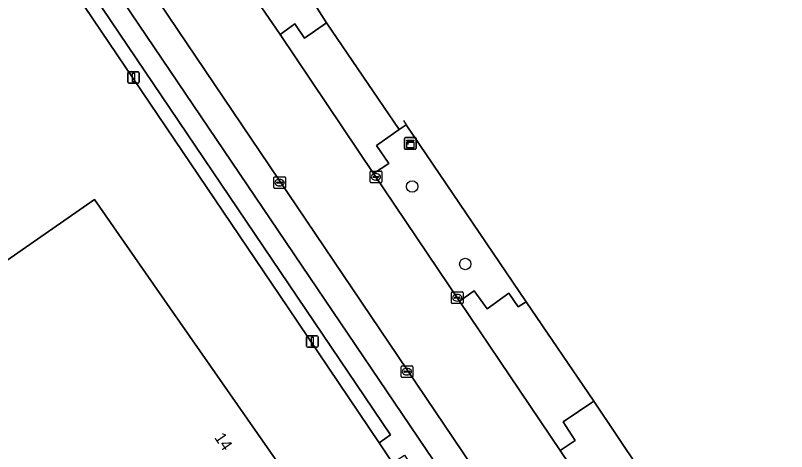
# Model space of a CAD drawing. Extents: x 156702 to 158052, y 387630 to 388992.
# Drawn here: x 157369.7 to 157436.1, y 387987.6 to 388025.2 of the extents above; entities that cross this region are included whole.
import ezdxf

# ---------------------------------------------------------------- set-up
doc = ezdxf.new("R2010")
doc.units = 0
for name, color, linetype in [('IMGEO_Berm_groen', 7, 'Continuous'), ('IMGEO_Boom', 7, 'Continuous'), ('IMGEO_Erf', 7, 'Continuous'), ('IMGEO_Groenvoorziening', 7, 'Continuous'), ('IMGEO_Hek', 7, 'Continuous'), ('IMGEO_Kast', 7, 'Continuous'), ('IMGEO_Kolk', 7, 'Continuous'), ('IMGEO_Lichtmast', 7, 'Continuous'), ('IMGEO_Pand', 7, 'Continuous'), ('IMGEO_Pand_nummerreeks', 7, 'Continuous'), ('IMGEO_Parkeervlak_open', 7, 'Continuous'), ('IMGEO_Rijbaan_lokaal_gesloten', 7, 'Continuous'), ('IMGEO_Rijbaan_lokaal_open', 7, 'Continuous'), ('IMGEO_Voetpad_open', 7, 'Continuous')]:
    doc.layers.add(name, color=color, linetype=linetype)

msp = doc.modelspace()

# ---------------------------------------------------------------- linework, layer by layer
at = {"layer": 'IMGEO_Berm_groen'}
for points in [[(157387.19, 388039.182), (157379.198, 388048.04), (157377.897, 388047.012), (157379.097, 388045.532), (157377.848, 388044.562), (157380.459, 388041.129), (157392.527, 388023.508), (157393.764, 388024.429), (157394.61, 388023.215), (157396.502, 388024.511)], [(157403.363, 388015.762), (157402.741, 388015.343), (157400.789, 388013.975), (157401.855, 388012.429), (157400.555, 388011.557), (157407.925, 388000.59), (157409.211, 388001.471), (157410.319, 387999.926), (157412.192, 388001.265), (157412.973, 388000.104), (157413.667, 388000.525)], [(157419.496, 387991.988), (157416.861, 387990.191), (157417.893, 387988.603), (157416.586, 387987.739), (157420.098, 387982.532), (157423.609, 387977.326), (157424.882, 387978.233), (157426.84, 387975.471), (157429.376, 387977.195)]]:
    msp.add_lwpolyline(points, close=True, dxfattribs=at)
at = {"layer": 'IMGEO_Boom'}
for centre in [(157403.868, 388010.441), (157408.434, 388003.776)]:
    msp.add_circle(centre, 0.489, dxfattribs=at)
at = {"layer": 'IMGEO_Erf'}
for points in [[(157387.19, 388039.182), (157396.502, 388024.511), (157402.741, 388015.343), (157403.363, 388015.762), (157413.667, 388000.525), (157419.496, 387991.988), (157429.376, 387977.195), (157434.667, 387969.272), (157436.067, 387967.176), (157433.406, 387964.883), (157433.59, 387964.667), (157433.73, 387964.762), (157434.042, 387964.343), (157428.255, 387959.385), (157427.905, 387959.765), (157428.127, 387959.953), (157427.939, 387960.171), (157427.645, 387960.512), (157423.765, 387957.199), (157400.278, 387936.844), (157388.261, 387926.646), (157368.779, 387910.004)], [(157410.18, 387974.784), (157402.177, 387986.679), (157401.025, 387988.392), (157393.215, 388000), (157371.506, 388032.159), (157369.928, 388034.292)], [(157368.332, 388003.627), (157376.541, 388009.329), (157383.04, 388000), (157393.139, 387985.505), (157395.632, 387981.926), (157397.057, 387982.917), (157398.504, 387980.872), (157399.026, 387981.234), (157403.012, 387975.51), (157402.494, 387975.151), (157405.159, 387971.263), (157401.506, 387968.719), (157398.499, 387966.625), (157378.578, 387952.75), (157377.05, 387954.95), (157374.897, 387958.052), (157370.981, 387963.692), (157367.677, 387961.4)]]:
    msp.add_lwpolyline(points, dxfattribs=at)
at = {"layer": 'IMGEO_Groenvoorziening'}
msp.add_lwpolyline([(157372.113, 388033.384), (157370.953, 388035.05), (157369.928, 388034.292), (157371.506, 388032.159), (157393.215, 388000), (157401.025, 387988.392), (157402.016, 387989.08)], close=True, dxfattribs=at)
at = {"layer": 'IMGEO_Hek'}
for points in [[(157403.125, 388016.114), (157403.363, 388015.762)], [(157403.363, 388015.762), (157413.667, 388000.525)], [(157413.667, 388000.525), (157419.496, 387991.988)], [(157419.496, 387991.988), (157436.067, 387967.176)]]:
    msp.add_lwpolyline(points, dxfattribs=at)
at = {"layer": 'IMGEO_Kast'}
for p, q in [((157403.214, 388013.726), (157403.214, 388014.567)), ((157403.214, 388014.567), (157403.214, 388013.726)), ((157403.289, 388014.651), (157404.13, 388014.651)), ((157404.13, 388014.651), (157403.289, 388014.651)), ((157404.214, 388014.576), (157404.214, 388013.735)), ((157404.214, 388013.735), (157404.214, 388014.576)), ((157404.139, 388013.651), (157403.298, 388013.651)), ((157403.298, 388013.651), (157404.139, 388013.651))]:
    msp.add_line(p, q, dxfattribs=at)
for points in [[(157403.409, 388014.441), (157404.009, 388014.441), (157404.009, 388014.356), (157403.409, 388014.356), (157403.409, 388014.441)], [(157403.409, 388014.266), (157404.009, 388014.266), (157404.009, 388013.777), (157403.409, 388013.777), (157403.409, 388014.266)]]:
    msp.add_lwpolyline(points, dxfattribs=at)
msp.add_circle((157403.493, 388014.115), 0.0377, dxfattribs=at)
for centre, start, end in [((157403.292, 388014.573), 92.4484, 184.28452), ((157403.292, 388014.573), 92.4484, 184.28452), ((157404.136, 388014.573), 2.4484, 94.28452), ((157404.136, 388014.573), 2.4484, 94.28452), ((157403.292, 388013.729), 182.4484, 274.28452), ((157403.292, 388013.729), 182.4484, 274.28452), ((157404.136, 388013.729), 272.4484, 4.28452), ((157404.136, 388013.729), 272.4484, 4.28452)]:
    msp.add_arc(centre, 0.0779, start, end, dxfattribs=at)
at = {"layer": 'IMGEO_Kolk'}
for p, q in [((157400.25, 388010.848), (157400.25, 388011.7)), ((157400.325, 388011.774), (157401.177, 388011.774)), ((157400.738, 388011.554), (157400.763, 388011.554)), ((157401.251, 388011.7), (157401.251, 388010.848)), ((157391.963, 388010.353), (157391.963, 388011.205)), ((157392.038, 388011.279), (157392.89, 388011.279)), ((157392.222, 388010.773), (157392.222, 388010.785)), ((157392.265, 388010.822), (157392.663, 388010.822)), ((157392.451, 388011.059), (157392.476, 388011.059)), ((157392.706, 388010.785), (157392.706, 388010.773)), ((157392.964, 388011.205), (157392.964, 388010.353)), ((157401.177, 388010.774), (157400.325, 388010.774)), ((157400.509, 388011.268), (157400.509, 388011.28)), ((157400.947, 388011.231), (157400.549, 388011.231)), ((157400.552, 388011.317), (157400.95, 388011.317)), ((157400.761, 388010.994), (157400.736, 388010.994)), ((157400.993, 388011.28), (157400.993, 388011.268)), ((157392.89, 388010.279), (157392.038, 388010.279)), ((157392.66, 388010.736), (157392.262, 388010.736)), ((157392.474, 388010.499), (157392.449, 388010.499)), ((157407.24, 388000.446), (157407.24, 388001.298)), ((157407.315, 388001.372), (157408.167, 388001.372)), ((157407.499, 388000.866), (157407.499, 388000.878)), ((157407.937, 388000.829), (157407.539, 388000.829)), ((157407.542, 388000.915), (157407.94, 388000.915)), ((157407.728, 388001.152), (157407.753, 388001.152)), ((157407.983, 388000.878), (157407.983, 388000.866)), ((157408.241, 388001.298), (157408.241, 388000.446)), ((157408.167, 388000.372), (157407.315, 388000.372)), ((157407.751, 388000.592), (157407.726, 388000.592)), ((157402.917, 387994.091), (157402.917, 387994.943)), ((157402.992, 387995.017), (157403.844, 387995.017)), ((157403.918, 387994.943), (157403.918, 387994.091)), ((157403.176, 387994.511), (157403.176, 387994.523)), ((157403.614, 387994.474), (157403.216, 387994.474)), ((157403.219, 387994.56), (157403.617, 387994.56)), ((157403.428, 387994.237), (157403.403, 387994.237)), ((157403.405, 387994.797), (157403.43, 387994.797)), ((157403.66, 387994.523), (157403.66, 387994.511)), ((157403.844, 387994.017), (157402.992, 387994.017))]:
    msp.add_line(p, q, dxfattribs=at)
for points in [[(157400.25, 388010.848), (157400.25, 388011.7)], [(157400.325, 388011.774), (157401.177, 388011.774)], [(157401.251, 388011.7), (157401.251, 388010.848)], [(157391.963, 388010.353), (157391.963, 388011.205)], [(157392.038, 388011.279), (157392.89, 388011.279)], [(157392.964, 388011.205), (157392.964, 388010.353)], [(157401.177, 388010.774), (157400.325, 388010.774)], [(157392.89, 388010.279), (157392.038, 388010.279)], [(157407.24, 388000.446), (157407.24, 388001.298)], [(157407.315, 388001.372), (157408.167, 388001.372)], [(157408.241, 388001.298), (157408.241, 388000.446)], [(157408.167, 388000.372), (157407.315, 388000.372)], [(157402.917, 387994.091), (157402.917, 387994.943)], [(157402.992, 387995.017), (157403.844, 387995.017)], [(157403.918, 387994.943), (157403.918, 387994.091)], [(157403.844, 387994.017), (157402.992, 387994.017)]]:
    msp.add_lwpolyline(points, dxfattribs=at)
for centre, radius, start, end in [((157400.327, 388011.698), 0.0765, 91.55205, 178.44795), ((157400.327, 388011.698), 0.0765, 91.55205, 178.44795), ((157401.175, 388011.698), 0.0765, 1.55205, 88.44795), ((157401.175, 388011.698), 0.0765, 1.55205, 88.44795), ((157392.04, 388011.203), 0.0765, 91.55205, 178.44795), ((157392.04, 388011.203), 0.0765, 91.55205, 178.44795), ((157392.262, 388010.782), 0.0403, 85.87752, 175.75265), ((157392.259, 388010.772), 0.0366, 178.93798, 274.71019), ((157392.663, 388010.779), 0.043, 264.86636, 352.45326), ((157392.667, 388010.784), 0.0386, 1.73085, 96.63898), ((157392.888, 388011.203), 0.0765, 1.55205, 88.44795), ((157392.888, 388011.203), 0.0765, 1.55205, 88.44795), ((157400.327, 388010.85), 0.0765, 181.55205, 268.44795), ((157400.327, 388010.85), 0.0765, 181.55205, 268.44795), ((157400.549, 388011.277), 0.0403, 85.87752, 175.75265), ((157400.546, 388011.267), 0.0366, 178.93798, 274.71019), ((157400.95, 388011.274), 0.043, 264.86636, 352.45326), ((157400.954, 388011.279), 0.0386, 1.73085, 96.63898), ((157401.175, 388010.85), 0.0765, 271.55205, 358.44795), ((157401.175, 388010.85), 0.0765, 271.55205, 358.44795), ((157392.04, 388010.355), 0.0765, 181.55205, 268.44795), ((157392.04, 388010.355), 0.0765, 181.55205, 268.44795), ((157392.888, 388010.355), 0.0765, 271.55205, 358.44795), ((157392.888, 388010.355), 0.0765, 271.55205, 358.44795), ((157407.317, 388001.296), 0.0765, 91.55205, 178.44795), ((157407.317, 388001.296), 0.0765, 91.55205, 178.44795), ((157407.539, 388000.875), 0.0403, 85.87752, 175.75265), ((157407.536, 388000.865), 0.0366, 178.93798, 274.71019), ((157407.94, 388000.872), 0.043, 264.86636, 352.45326), ((157407.944, 388000.877), 0.0386, 1.73085, 96.63898), ((157408.165, 388001.296), 0.0765, 1.55205, 88.44795), ((157408.165, 388001.296), 0.0765, 1.55205, 88.44795), ((157407.317, 388000.448), 0.0765, 181.55205, 268.44795), ((157407.317, 388000.448), 0.0765, 181.55205, 268.44795), ((157408.165, 388000.448), 0.0765, 271.55205, 358.44795), ((157408.165, 388000.448), 0.0765, 271.55205, 358.44795), ((157402.994, 387994.941), 0.0765, 91.55205, 178.44795), ((157402.994, 387994.941), 0.0765, 91.55205, 178.44795), ((157403.842, 387994.941), 0.0765, 1.55205, 88.44795), ((157403.842, 387994.941), 0.0765, 1.55205, 88.44795), ((157403.216, 387994.52), 0.0403, 85.87752, 175.75265), ((157403.213, 387994.51), 0.0366, 178.93798, 274.71019), ((157403.617, 387994.517), 0.043, 264.86636, 352.45326), ((157403.621, 387994.522), 0.0386, 1.73085, 96.63898), ((157402.994, 387994.093), 0.0765, 181.55205, 268.44795), ((157402.994, 387994.093), 0.0765, 181.55205, 268.44795), ((157403.842, 387994.093), 0.0765, 271.55205, 358.44795), ((157403.842, 387994.093), 0.0765, 271.55205, 358.44795)]:
    msp.add_arc(centre, radius, start, end, dxfattribs=at)
for centre, major_axis, ratio, start_param, end_param in [((157400.737, 388011.274), (-0.387, 0.002), 0.722429, 4.712389, 7.853982), ((157400.762, 388011.274), (-0.39, 0.002), 0.717154, 1.570796, 4.712389), ((157392.45, 388010.779), (-0.387, 0.002), 0.722429, 4.712389, 7.853982), ((157392.475, 388010.779), (-0.39, 0.002), 0.717154, 1.570796, 4.712389), ((157407.727, 388000.872), (-0.387, 0.002), 0.722429, 4.712389, 7.853982), ((157407.752, 388000.872), (-0.39, 0.002), 0.717154, 1.570796, 4.712389), ((157403.404, 387994.517), (-0.387, 0.002), 0.722429, 4.712389, 7.853982), ((157403.429, 387994.517), (-0.39, 0.002), 0.717154, 1.570796, 4.712389)]:
    msp.add_ellipse(centre, major_axis=major_axis, ratio=ratio, start_param=start_param, end_param=end_param, dxfattribs=at)
at = {"layer": 'IMGEO_Lichtmast'}
for p, q in [((157379.409, 388019.423), (157379.409, 388020.223)), ((157379.409, 388020.223), (157379.409, 388019.423)), ((157379.509, 388020.323), (157380.299, 388020.323)), ((157380.299, 388020.323), (157379.509, 388020.323)), ((157380.399, 388020.223), (157380.399, 388019.423)), ((157380.399, 388019.423), (157380.399, 388020.223)), ((157380.299, 388019.323), (157379.509, 388019.323)), ((157379.509, 388019.323), (157380.299, 388019.323)), ((157394.782, 387996.71), (157394.782, 387997.51)), ((157394.782, 387997.51), (157394.782, 387996.71)), ((157394.882, 387997.61), (157395.672, 387997.61)), ((157395.672, 387997.61), (157394.882, 387997.61)), ((157395.772, 387997.51), (157395.772, 387996.71)), ((157395.772, 387996.71), (157395.772, 387997.51)), ((157395.672, 387996.61), (157394.882, 387996.61)), ((157394.882, 387996.61), (157395.672, 387996.61))]:
    msp.add_line(p, q, dxfattribs=at)
for points in [[(157379.829, 388020.198), (157379.979, 388020.198), (157379.979, 388019.448), (157379.829, 388019.448), (157379.829, 388020.198)], [(157395.202, 387997.485), (157395.352, 387997.485), (157395.352, 387996.735), (157395.202, 387996.735), (157395.202, 387997.485)]]:
    msp.add_lwpolyline(points, dxfattribs=at)
for centre, start, end in [((157379.509, 388020.223), 90, 180), ((157379.509, 388020.223), 90, 180), ((157380.299, 388020.223), 0, 90), ((157380.299, 388020.223), 360, 90), ((157379.509, 388019.423), 180, 270), ((157379.509, 388019.423), 180, 270), ((157380.299, 388019.423), 270, 0), ((157380.299, 388019.423), 270, 0), ((157394.882, 387997.51), 90, 180), ((157394.882, 387997.51), 90, 180), ((157395.672, 387997.51), 0, 90), ((157395.672, 387997.51), 360, 90), ((157394.882, 387996.71), 180, 270), ((157394.882, 387996.71), 180, 270), ((157395.672, 387996.71), 270, 0), ((157395.672, 387996.71), 270, 0)]:
    msp.add_arc(centre, 0.1, start, end, dxfattribs=at)
at = {"layer": 'IMGEO_Pand'}
msp.add_lwpolyline([(157367.677, 387961.4), (157370.981, 387963.692), (157374.897, 387958.052), (157377.05, 387954.95), (157378.578, 387952.75), (157398.499, 387966.625), (157401.506, 387968.719), (157405.159, 387971.263), (157402.494, 387975.151), (157403.012, 387975.51), (157399.026, 387981.234), (157398.504, 387980.872), (157397.057, 387982.917), (157395.632, 387981.926), (157393.139, 387985.505), (157383.04, 388000), (157376.541, 388009.329), (157368.332, 388003.627)], dxfattribs=at)
at = {"layer": 'IMGEO_Parkeervlak_open'}
for points in [[(157375.784, 388035.713), (157373.667, 388034.286), (157409.026, 387981.971)], [(157412.951, 387980.565), (157375.784, 388035.713)]]:
    msp.add_lwpolyline(points, dxfattribs=at)
at = {"layer": 'IMGEO_Rijbaan_lokaal_gesloten'}
msp.add_lwpolyline([(157375.701, 388035.836), (157375.784, 388035.713), (157412.951, 387980.565), (157414.43, 387978.195), (157420.098, 387982.532), (157416.586, 387987.739), (157407.925, 388000.59), (157400.555, 388011.557), (157392.527, 388023.508), (157380.459, 388041.129), (157377.848, 388044.562)], dxfattribs=at)
at = {"layer": 'IMGEO_Rijbaan_lokaal_open'}
for points in [[(157400.555, 388011.557), (157401.855, 388012.429), (157400.789, 388013.975), (157402.741, 388015.343), (157396.502, 388024.511), (157394.61, 388023.215), (157393.764, 388024.429), (157392.527, 388023.508)], [(157416.586, 387987.739), (157417.893, 387988.603), (157416.861, 387990.191), (157419.496, 387991.988), (157413.667, 388000.525), (157412.973, 388000.104), (157412.192, 388001.265), (157410.319, 387999.926), (157409.211, 388001.471), (157407.925, 388000.59)]]:
    msp.add_lwpolyline(points, close=True, dxfattribs=at)
at = {"layer": 'IMGEO_Voetpad_open'}
msp.add_lwpolyline([(157409.026, 387981.971), (157373.667, 388034.286), (157373.583, 388034.411), (157372.113, 388033.384), (157402.016, 387989.08), (157401.025, 387988.392), (157402.177, 387986.679), (157403.198, 387987.328), (157411.206, 387975.464), (157410.18, 387974.784)], dxfattribs=at)

# ---------------------------------------------------------------- texts
at = {"layer": 'IMGEO_Pand_nummerreeks'}
msp.add_text('14', height=1, rotation=304.85281, dxfattribs=at).set_placement((157386.811, 387988.843))

doc.saveas('drawing.dxf')
